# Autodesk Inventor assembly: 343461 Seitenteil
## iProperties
Company: Mayer & Müller AG
Created: 2006-03
Part Number: 343461 Seitenteil
Document SubType Name: Weldment
Designer: I.Baliuc
Description: Seitenteil, kompl. (links)
Material: Geschweißt
Cost Center: 2,135 kg
Authority: 272373 mm^3
Mass: 2103.96 g
Surface Area: 1820.01 cm^2
Volume: 268.361 cm^3
Density: 7.84002 g/cm^3
Zweck: Vorkontakt HSLT
SaveDate: 2006-10-28
SaveTime: 21:32
TotalMass: 2,135 kg
TotalVolume: 272373 mm^3
Author: T.Messerschmitt
Revision Number: 343461
